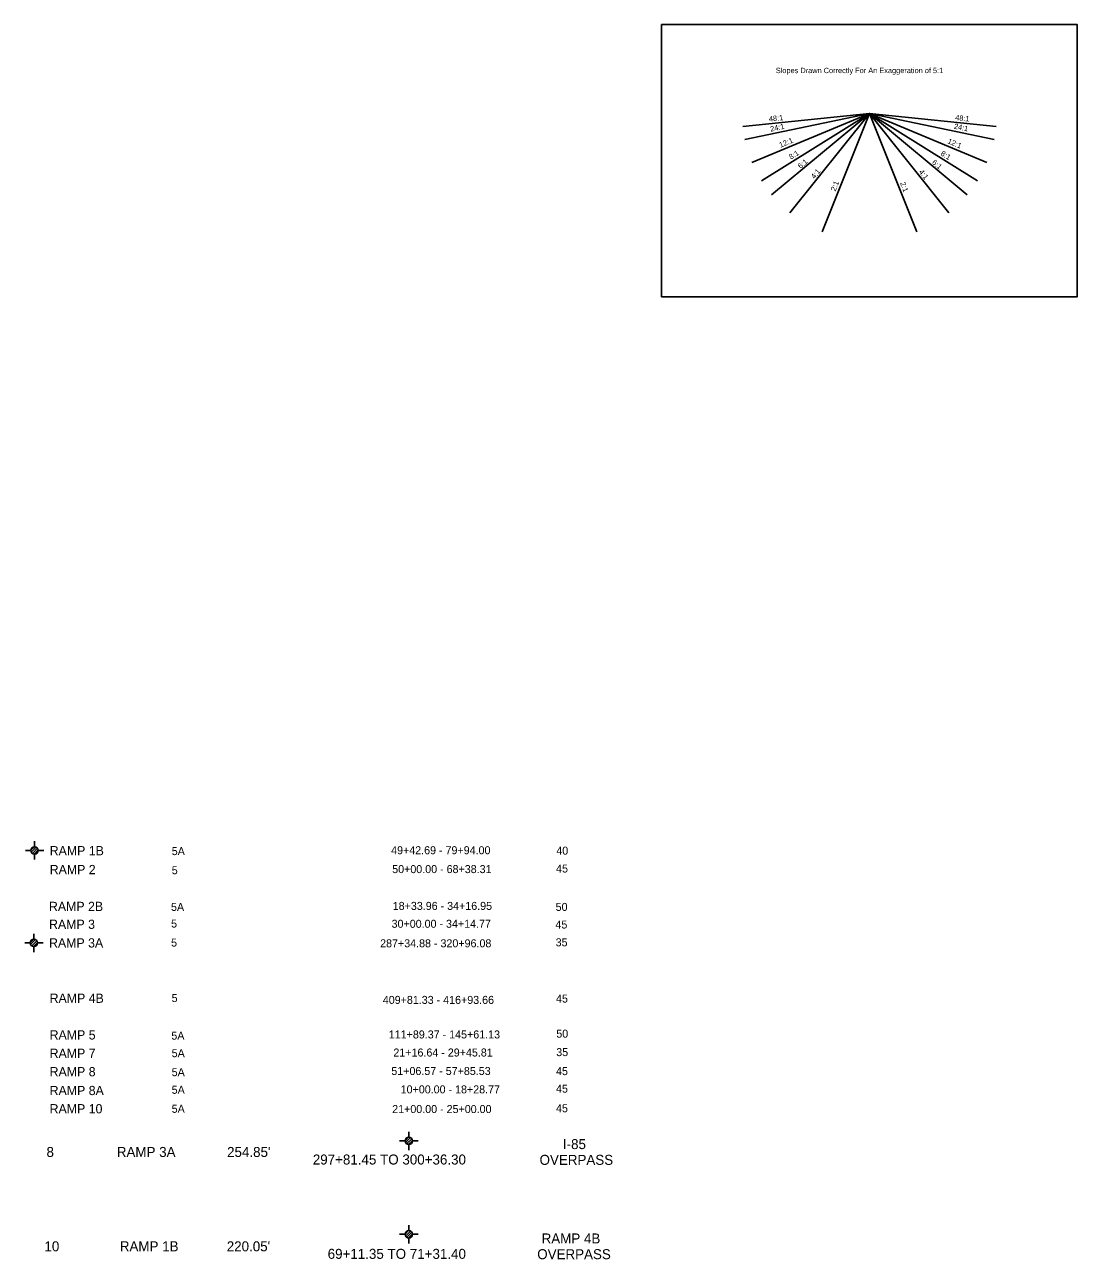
# Model space of a CAD drawing. Extents: x 4649 to 5578, y 4853 to 5383.
# Drawn here: x 5350.3 to 5508.2, y 4877.3 to 5062.5 of the extents above; entities that cross this region are included whole.
import ezdxf

# ---------------------------------------------------------------- set-up
doc = ezdxf.new("R2010")
doc.units = 0
for name, color, linetype in [('Level 3', 7, 'Continuous'), ('RD_EX_SU_Pole', 7, 'Continuous'), ('RD_SHT_Typical', 7, 'Continuous'), ('RD_TX_TypSect', 7, 'Continuous')]:
    doc.layers.add(name, color=color, linetype=linetype)

# ---------------------------------------------------------------- blocks, each defined once
blk = doc.blocks.new('SUE_TFP')
at = {"layer": 'RD_EX_SU_Pole'}
for p, q in [((-2.21, 0.13), (-0.13, 2.21)), ((-1.96, -1.03), (1.03, 1.96)), ((-1.31, -1.79), (1.79, 1.31)), ((-0.3, -2.2), (2.2, 0.3)), ((0, 5.5), (0, 2.22)), ((2.22, 0), (5.53, 0.01)), ((-5.53, -0.01), (-2.22, 0)), ((0, -2.22), (0, -5.5))]:
    blk.add_line(p, q, dxfattribs=at)
blk.add_circle((0, 0), 2.22, dxfattribs=at)

msp = doc.modelspace()

# ---------------------------------------------------------------- linework, layer by layer
at = {"layer": 'RD_SHT_Typical'}
for q in [(5458, 5047.17), (5458.3, 5045.25), (5459.37, 5041.8), (5460.8, 5039.02), (5462.33, 5036.92), (5465.07, 5034.23), (5469.91, 5031.41), (5484.1, 5031.41), (5494.64, 5041.8), (5488.94, 5034.23), (5491.68, 5036.92), (5493.2, 5039.02), (5495.71, 5045.25), (5496, 5047.17)]:
    msp.add_line((5477, 5049.15), q, dxfattribs=at)
msp.add_lwpolyline([(5445.82, 5062.46), (5508.19, 5062.46), (5508.19, 5021.65), (5445.82, 5021.65)], close=True, dxfattribs=at)

# ---------------------------------------------------------------- block references
at = {"layer": 'Level 3', "xscale": 0.2499999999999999, "yscale": 0.2499999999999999}
for p in [(5351.76, 4938.59), (5351.66, 4924.73), (5407.9, 4895.03), (5407.91, 4881.02)]:
    msp.add_blockref('SUE_TFP', p, dxfattribs=at)

# ---------------------------------------------------------------- texts
at = {"layer": 'Level 3'}
for s, p in [('I-85 ', (5431.02, 4893.8)), ('8', (5353.55, 4892.62)), ('RAMP 3A', (5364.1, 4892.62)), ("254.85'", (5380.64, 4892.62)), ('297+81.45 TO 300+36.30', (5393.5, 4891.49)), ('OVERPASS', (5427.52, 4891.44)), ('10', (5353.24, 4878.47)), ('RAMP 1B', (5364.55, 4878.47)), ('RAMP 1B', (5364.55, 4878.47)), ("220.05'", (5380.59, 4878.47)), ('RAMP 4B ', (5427.83, 4879.65)), ('69+11.35 TO 71+31.40', (5395.73, 4877.34)), ('OVERPASS', (5427.17, 4877.29))]:
    msp.add_text(s, height=1.5, dxfattribs=at).set_placement(p)
at = {"layer": 'RD_TX_TypSect'}
for s, height, p in [('Slopes Drawn Correctly For An Exaggeration of 5:1', 0.8, (5462.96, 5055.19)), ('RAMP 1B', 1.384, (5354.03, 4937.87)), ('5A', 1.2, (5372.34, 4937.9)), ('49+42.69 - 79+94.00', 1.2, (5405.25, 4938.03)), ('40', 1.2, (5430.03, 4937.97)), ('RAMP 2', 1.384, (5354.03, 4935.04)), ('5', 1.2, (5372.34, 4935.03)), ('50+00.00 - 68+38.31', 1.2, (5405.41, 4935.2)), ('45', 1.2, (5430, 4935.29)), ('RAMP 2B', 1.384, (5353.92, 4929.51)), ('5A', 1.2, (5372.23, 4929.53)), ('18+33.96 - 34+16.95', 1.2, (5405.49, 4929.68)), ('50', 1.2, (5429.93, 4929.53)), ('RAMP 3', 1.384, (5353.93, 4926.83)), ('5', 1.2, (5372.24, 4927.03)), ('30+00.00 - 34+14.77', 1.2, (5405.32, 4927)), ('45', 1.2, (5429.9, 4926.89)), ('RAMP 3A', 1.384, (5353.93, 4924.04)), ('5', 1.2, (5372.24, 4924.18)), ('287+34.88 - 320+96.08', 1.2, (5403.6, 4924.07)), ('35', 1.2, (5429.93, 4924.22)), ('RAMP 4B', 1.384, (5354.02, 4915.74)), ('5', 1.2, (5372.32, 4915.86)), ('409+81.33 - 416+93.66', 1.2, (5404, 4915.58)), ('45', 1.2, (5429.99, 4915.78)), ('RAMP 5', 1.384, (5354.02, 4910.24)), ('5A', 1.2, (5372.28, 4910.22)), ('111+89.37 - 145+61.13', 1.2, (5404.9, 4910.4)), ('50', 1.2, (5430.03, 4910.52)), ('RAMP 7', 1.384, (5354.02, 4907.48)), ('5A', 1.2, (5372.33, 4907.59)), ('21+16.64 - 29+45.81', 1.2, (5405.59, 4907.69)), ('35', 1.2, (5430.02, 4907.75)), ('RAMP 8', 1.384, (5354.02, 4904.72)), ('5A', 1.2, (5372.33, 4904.74)), ('51+06.57 - 57+85.53', 1.2, (5405.28, 4904.92)), ('45', 1.2, (5429.99, 4904.9)), ('RAMP 8A', 1.384, (5354.02, 4901.9)), ('5A', 1.2, (5372.33, 4902.1)), ('10+00.00 - 18+28.77', 1.2, (5406.68, 4902.16)), ('45', 1.2, (5429.99, 4902.27)), ('RAMP 10', 1.384, (5354.02, 4899.16)), ('5A', 1.2, (5372.33, 4899.25)), ('21+00.00 - 25+00.00', 1.2, (5405.41, 4899.21)), ('45', 1.2, (5429.99, 4899.33))]:
    msp.add_text(s, height=height, dxfattribs=at).set_placement(p)
for s, rotation, p in [('48:1', 5.9469, (5461.96, 5047.92)), ('48:1', 354.0531, (5489.84, 5048.15)), ('24:1', 11.7683, (5462.21, 5046.41)), ('24:1', 348.2317, (5489.63, 5046.87)), ('12:1', 22.6199, (5463.66, 5043.99)), ('12:1', 337.3801, (5488.65, 5044.69)), ('8:1', 32.0054, (5465.23, 5042.19)), ('8:1', 327.9946, (5487.6, 5042.93)), ('6:1', 39.8056, (5466.66, 5040.81)), ('4:1', 51.3402, (5468.76, 5039.24)), ('6:1', 320.1944, (5486.31, 5041.67)), ('2:1', 291.8014, (5481.59, 5038.69)), ('4:1', 308.6598, (5484.36, 5040.35)), ('2:1', 68.1986, (5471.9, 5037.4))]:
    msp.add_text(s, height=0.8, rotation=rotation, dxfattribs=at).set_placement(p)

doc.saveas('drawing.dxf')
